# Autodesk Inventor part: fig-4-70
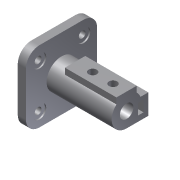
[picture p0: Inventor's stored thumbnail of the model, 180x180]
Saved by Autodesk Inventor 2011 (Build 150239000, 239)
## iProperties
Shininess: 77.0
Length Units: 11269
Angle Units: 11279
Time Units: 11290
Mass Units: 11283
Length Display Precision: 3
Angle Display Precision: 2
Created: 2001-12
Part Number: fig-4-70
Document SubType Name: Modeling
Designer: Renu Muthoo
Density: 1 g/cm^3
Density: 0.0
Volumn: 0.0
Area: 0.0
PropertySet Name: Model Information
Control State: 0
Master: False
Checked Out: False
Author: Renu Muthoo
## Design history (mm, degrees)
node "Sketch1"
sketch "Sketch2"
  geometry: L1 (24.44, 30.488)-(-40.56, 30.488); L2 (-60.56, 10.488)-(-60.56, -54.512); L3 (-40.56, -74.512)-(24.44, -74.512); L4 (44.44, -54.512)-(44.44, 10.488); A1 r 20 centre (24.44, 10.488) between (44.44, 10.488) and (24.44, 30.488); A2 r 20 centre (-40.56, 10.488) between (-40.56, 30.488) and (-60.56, 10.488); A3 r 20 centre (-40.56, -54.512) between (-60.56, -54.512) and (-40.56, -74.512); A4 r 20 centre (24.44, -54.512) between (24.44, -74.512) and (44.44, -54.512); 2 further points
  constraints: 8 end point, 8 point on circle, 8 tangent, 4 centre point, 4 point on line, 3 equal radius, 2 parallel, 2 perpendicular, 1 horizontal
  dimensions: "d1" = 20 radius of A1; "d2" = 105 distance between parallel lines of L2 L4
extrude "Extrusion1" new body sketch "Sketch2" distance "d3" = 12; taper "d4" = 0 deg
sketch "Sketch3"
  geometry: A1 r 20 centre (-24.44, 10.488) between (-24.44, 30.488) and (-44.44, 10.488) reference; A2 r 20 centre (-24.44, -54.512) between (-44.44, -54.512) and (-24.44, -74.512) reference; A3 r 20 centre (40.56, -54.512) between (40.56, -74.512) and (60.56, -54.512) reference; A4 r 20 centre (40.56, 10.488) between (60.56, 10.488) and (40.56, 30.488) reference
hole "Hole1" sketch "Sketch3" at (-24.44, 10.488), (-24.44, -54.512), (40.56, 10.488), (40.56, -54.512) diameter "d5" = 10; stored, may be unused: countersink angle "d9" = 82 deg, drill point angle "d11" = 118 deg; dims "d6" = 6, "d7" = 20, "d8" = 2, "d10" = 8
sketch "Sketch4"
  geometry: L1 (-24.44, 30.488)-(40.56, 30.488) reference; L2 (-44.44, -54.512)-(-44.44, 10.488) reference; C1 r 22 at (8.06, -22.012)
  constraints: 1 centre point
  dimensions: "d12" = 52.5 distance from line of L2 C1.centre; "d13" = 52.5 distance from line of L1 C1.centre; "d14" = 44 diameter of C1
extrude "Extrusion2" join sketch "Sketch4" distance "d15" = 96; taper "d16" = 0 deg
sketch "Sketch5"
  geometry: L1 (-15, 16.093)-(15, 16.093); L2 (15, 16.093)-(15, 25); L3 (15, 25)-(-15, 25); L4 (-15, 25)-(-15, 16.093); 1 further point
  constraints: 8 end point, 2 parallel, 1 horizontal, 1 perpendicular, 2 other
  dimensions: "d17" = 30 distance of L2.end L3.end; "d18" = 25 distance from line of point (0, 0) L3; "d19" = 15 distance from line of point (0, 0) L4
extrude "Extrusion3" join sketch "Sketch5" distance "d20" = 76; taper "d21" = 0 deg
sketch "Sketch6"
  geometry: L1 (8, -44.012)-(40.06, -44.012); L2 (40.06, -44.012)-(40.06, -14.012); L3 (40.06, -14.012)-(8, -14.012); L4 (8, -14.012)-(8, -44.012); A1 r 22 centre (8.06, -22.012) between (-6.94, -5.918) and (23.06, -5.918) reference
  constraints: 8 end point, 2 parallel, 1 horizontal, 1 perpendicular, 1 tangent
  dimensions: "d22" = 32 distance from line of A1.centre L2; "d23" = 30 distance of L1.end L2.end
extrude "Extrusion4" join sketch "Sketch6" distance "d24" = 57; taper "d25" = 0 deg
sketch "Sketch7"
  geometry: L1 (25.06, -20.012)-(33.06, -20.012); L2 (33.06, -20.012)-(33.06, -36.012); L3 (33.06, -36.012)-(25.06, -36.012); L4 (25.06, -36.012)-(25.06, -20.012); A1 r 22 centre (8.06, -22.012) between (-6.94, -5.918) and (8, -44.012) reference
  constraints: 8 end point, 2 parallel, 1 horizontal, 1 perpendicular
  dimensions: "d26" = 8 distance of L2.end L3.end; "d27" = 16 distance of L1.end L2.end; "d28" = 25 distance from line of A1.centre L2; "d29" = 2 vertical distance of A1.centre L1.start
extrude "Extrusion5" cut sketch "Sketch7" distance "d30" = 35; taper "d31" = 0 deg
sketch "Sketch8"
  geometry: A1 r 22 centre (8.06, -22.012) between (-6.94, -5.918) and (8, -44.012) reference
hole "Hole2" sketch "Sketch8" at (8.06, -22.012) diameter "d32" = 20; stored, may be unused: countersink angle "d36" = 82 deg, drill point angle "d38" = 0 deg; dims "d33" = 6, "d34" = 20, "d35" = 2, "d37" = 96
sketch "Sketch9"
  geometry: L1 (0, 0)-(0, 76) reference; L2 (30, 0)-(0, 0) reference; 2 further points
  dimensions: "d39" = 20 distance from line of L2 point (15, 20); "d40" = 15 distance from line of L1 point (15, 20); "d41" = 30 distance of point (15, 50) point (15, 20)
hole "Hole3" sketch "Sketch9" at (15, 20), (15, 50) diameter "d42" = 12; stored, may be unused: countersink angle "d46" = 82 deg, drill point angle "d48" = 0 deg; dims "d43" = 6, "d44" = 20, "d45" = 2, "d47" = 25
sketch "Sketch10"
  geometry: L1 (30, 0)-(0, 0) reference; L2 (30, 0)-(30, 57) reference; 2 further points
  dimensions: "d49" = 15 distance from line of L1 point (15, 15); "d50" = 15 distance from line of L2 point (15, 15); "d51" = 22 distance of point (15, 37) point (15, 15)
hole "Hole4" sketch "Sketch10" at (15, 15), (15, 37) diameter "d52" = 10; stored, may be unused: countersink angle "d56" = 82 deg, drill point angle "d58" = 0 deg; dims "d53" = 6, "d54" = 20, "d55" = 2, "d57" = 7
body "Solid1"
